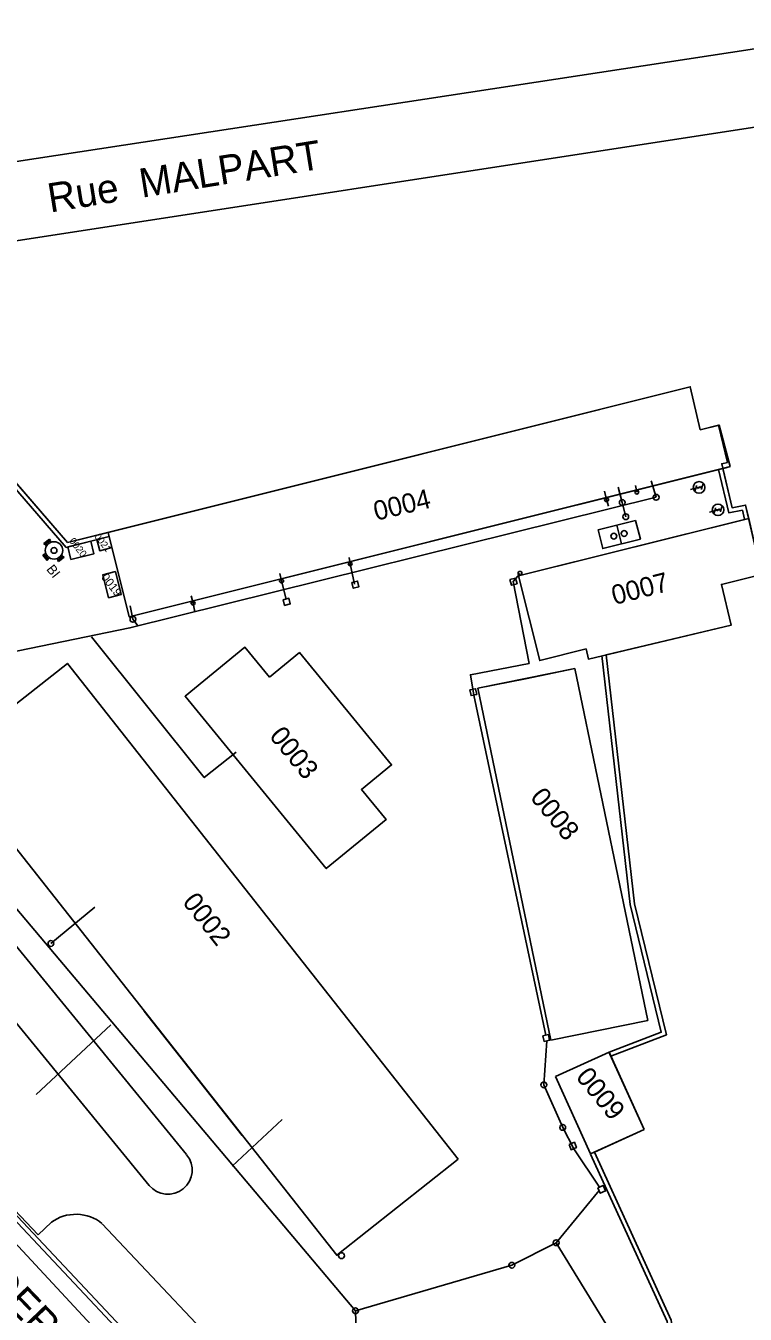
# Model space of a CAD drawing. Extents: x 703432 to 707394, y 7057985 to 7059523.
# Drawn here: x 704507 to 704581.3, y 7058975.3 to 7059108.3 of the extents above; entities that cross this region are included whole.
import ezdxf

# ---------------------------------------------------------------- set-up
doc = ezdxf.new("R2010")
doc.units = 0
for name, color, linetype in [('DH_HACHURE-MOTIF', 7, 'Continuous'), ('DH_TEXTE', 7, 'Continuous'), ('GEOSID_AIRE_AMENAGEE_POLYGONE', 7, 'Continuous'), ('GO_DALLE', 7, 'Continuous'), ('GO_MUR_EXTERIEUR', 7, 'Continuous'), ('IMM_LIMITE PHYSIQUE', 7, 'Continuous'), ('R_PLU_CANALISATION_CL_A', 7, 'Continuous'), ('RES_EAU BASSE PRESSION', 7, 'Continuous'), ('RES_EAU BASSE PRESSION - EQUIP - TEXTE', 7, 'Continuous'), ('RES_INCENDIE - EQUIP - TEXTE', 7, 'Continuous'), ('SID_NUMERO_BATI', 7, 'Continuous'), ('SID_POLYLIGNES_BATI', 7, 'Continuous'), ('SID_POLYLIGNES_IMMEUBLE', 7, 'Continuous'), ('SO_EP_EQUIP', 7, 'Continuous'), ('VOIRIE_BORDURE', 7, 'Continuous'), ('VOIRIE_ROUTE', 7, 'Continuous')]:
    doc.layers.add(name, color=color, linetype=linetype)

msp = doc.modelspace()

# ---------------------------------------------------------------- linework, layer by layer
at = {"layer": 'DH_HACHURE-MOTIF'}
for p, q in [((704553.67, 7059039.96), (704558.58, 7059040.92)), ((704561.21, 7059003.63), (704553.67, 7059039.96)), ((704571.23, 7059005.64), (704561.21, 7059003.63)), ((704561.7, 7058999.87), (704567.23, 7059002.37)), ((704565.31, 7058991.89), (704561.7, 7058999.87)), ((704570.84, 7058994.39), (704565.31, 7058991.89))]:
    msp.add_line(p, q, dxfattribs=at)
for points in [[(704515.58, 7059055.6), (704515.87, 7059054.46), (704517.65, 7059047.3), (704579.31, 7059062.71), (704579.74, 7059062.82), (704578.59, 7059067.1), (704576.65, 7059066.62), (704575.62, 7059071.07), (704538.76, 7059061.85), (704515.47, 7059056.03), (704515.58, 7059055.6)], [(704564.85, 7059044.01), (704565.09, 7059042.95), (704579.84, 7059046.44), (704578.84, 7059050.66), (704582.98, 7059051.69), (704581.66, 7059057.48), (704581.22, 7059057.37), (704557.88, 7059051.53), (704560.06, 7059042.8), (704564.85, 7059044.01)], [(704513.69, 7059055.12), (704511.31, 7059054.53), (704511.63, 7059053.24), (704514.01, 7059053.83), (704513.69, 7059055.12)], [(704515.52, 7059049.28), (704516.81, 7059049.61), (704516.22, 7059051.98), (704514.93, 7059051.66), (704515.52, 7059049.28)], [(704532.15, 7059041.09), (704529.61, 7059044.18), (704523.42, 7059039.11), (704538, 7059021.32), (704544.19, 7059026.39), (704541.65, 7059029.48), (704544.75, 7059032.02), (704535.24, 7059043.62), (704532.15, 7059041.09)], [(704551.65, 7058991.33), (704511.27, 7059042.51), (704505.27, 7059037.77), (704505.89, 7059036.98), (704499.33, 7059031.81), (704539.09, 7058981.42), (704551.65, 7058991.33)], [(704558.58, 7059040.92), (704563.69, 7059041.98), (704571.23, 7059005.64)], [(704567.23, 7059002.37), (704567.32, 7059002.18), (704570.84, 7058994.39)]]:
    msp.add_lwpolyline(points, dxfattribs=at)
at = {"layer": 'GEOSID_AIRE_AMENAGEE_POLYGONE'}
msp.add_lwpolyline([(704514.6, 7059054.14), (704514.32, 7059055.28), (704515.58, 7059055.6), (704515.86, 7059054.46)], close=True, dxfattribs=at)
at = {"layer": 'GO_DALLE'}
msp.add_lwpolyline([(704515.58, 7059055.6), (704515.87, 7059054.46), (704514.6, 7059054.14), (704514.32, 7059055.28)], close=True, dxfattribs=at)
at = {"layer": 'GO_MUR_EXTERIEUR'}
for p, q in [((704575.62, 7059071.07), (704515.47, 7059056.03)), ((704576.65, 7059066.62), (704575.62, 7059071.07)), ((704578.59, 7059067.1), (704576.65, 7059066.62)), ((704579.74, 7059062.82), (704578.59, 7059067.1)), ((704517.65, 7059047.3), (704579.74, 7059062.82)), ((704557.88, 7059051.53), (704581.66, 7059057.48)), ((704515.47, 7059056.03), (704517.65, 7059047.3)), ((704560.06, 7059042.8), (704557.88, 7059051.53)), ((704582.98, 7059051.69), (704578.84, 7059050.66)), ((704578.84, 7059050.66), (704579.84, 7059046.44)), ((704523.42, 7059039.11), (704529.61, 7059044.18)), ((704529.61, 7059044.18), (704532.15, 7059041.09)), ((704532.15, 7059041.09), (704535.24, 7059043.62)), ((704535.24, 7059043.62), (704544.75, 7059032.02)), ((704511.27, 7059042.51), (704505.27, 7059037.77)), ((704551.65, 7058991.33), (704511.27, 7059042.51)), ((704553.67, 7059039.96), (704563.69, 7059041.98)), ((704563.69, 7059041.98), (704571.23, 7059005.64)), ((704561.21, 7059003.63), (704553.67, 7059039.96)), ((704538, 7059021.32), (704523.42, 7059039.11)), ((704499.33, 7059031.81), (704539.09, 7058981.42)), ((704544.75, 7059032.02), (704541.65, 7059029.48)), ((704541.65, 7059029.48), (704544.19, 7059026.39)), ((704544.19, 7059026.39), (704538, 7059021.32)), ((704571.23, 7059005.64), (704561.21, 7059003.63)), ((704561.7, 7058999.87), (704567.23, 7059002.37)), ((704567.23, 7059002.37), (704570.84, 7058994.39)), ((704565.31, 7058991.89), (704561.7, 7058999.87)), ((704570.84, 7058994.39), (704565.31, 7058991.89)), ((704539.09, 7058981.42), (704551.65, 7058991.33))]:
    msp.add_line(p, q, dxfattribs=at)
for points in [[(704511.31, 7059054.53), (704511.63, 7059053.24), (704514.01, 7059053.83), (704513.69, 7059055.12)], [(704516.22, 7059051.98), (704514.93, 7059051.66), (704515.52, 7059049.28), (704516.81, 7059049.61)]]:
    msp.add_lwpolyline(points, close=True, dxfattribs=at)
msp.add_lwpolyline([(704579.84, 7059046.44), (704565.09, 7059042.95), (704564.85, 7059044.01), (704560.06, 7059042.8)], dxfattribs=at)
at = {"layer": 'IMM_LIMITE PHYSIQUE'}
for p, q in [((704499.39, 7059068.01), (704511.13, 7059054.48)), ((704499.74, 7059068.3), (704511.28, 7059054.99)), ((704515.59, 7059055.6), (704511.13, 7059054.48)), ((704515.47, 7059056.03), (704511.28, 7059054.99)), ((704472.61, 7059020.9), (704536.21, 7058953.48)), ((704472.28, 7059020.59), (704535.98, 7058953.07))]:
    msp.add_line(p, q, dxfattribs=at)
for points in [[(704578.55, 7059062.53), (704579.6, 7059058.05), (704581, 7059058.32), (704581.22, 7059057.38)], [(704578.99, 7059062.63), (704579.94, 7059058.58), (704581.34, 7059058.85), (704581.66, 7059057.48)], [(704566.47, 7059043.33), (704569.4, 7059017.61), (704572.62, 7059004.43), (704567.24, 7059002.38)], [(704566.92, 7059043.38), (704569.84, 7059017.69), (704573.15, 7059004.16), (704567.4, 7059001.96)], [(704574.25, 7058967.23), (704573.22, 7058974.58), (704565.32, 7058991.86)], [(704574.7, 7058967.3), (704573.66, 7058974.71), (704565.73, 7058992.05)]]:
    msp.add_lwpolyline(points, dxfattribs=at)
at = {"layer": 'R_PLU_CANALISATION_CL_A'}
for p, q in [((704568.59, 7059059.11), (704568.17, 7059060.71)), ((704570.1, 7059060.19), (704569.97, 7059060.88)), ((704572.09, 7059059.65), (704571.58, 7059061.35)), ((704566.97, 7059059.41), (704566.75, 7059060.27)), ((704566.97, 7059059.41), (704567.18, 7059058.73)), ((704568.59, 7059059.11), (704568.95, 7059057.65)), ((704568.03, 7059056.78), (704568.52, 7059054.84)), ((704540.48, 7059052.79), (704540.36, 7059053.44)), ((704540.48, 7059052.79), (704540.94, 7059050.67)), ((704533.39, 7059051.02), (704533.2, 7059051.8)), ((704558.03, 7059051.8), (704557.33, 7059050.95)), ((704533.39, 7059051.02), (704533.86, 7059049.15)), ((704524.25, 7059048.73), (704524.06, 7059049.47)), ((704524.25, 7059048.73), (704524.43, 7059047.8)), ((704518.04, 7059047.06), (704517.76, 7059048.45)), ((704518.04, 7059047.06), (704518.59, 7059046.36)), ((704553.26, 7059039.24), (704560.68, 7059004.13)), ((704500.69, 7059023.41), (704541.03, 7058975.68)), ((704509.56, 7059013.59), (704514.11, 7059017.35)), ((704519.21, 7059006.61), (704529.33, 7058993.79)), ((704515.74, 7059005.19), (704508.03, 7058998)), ((704533.45, 7058995.41), (704528.29, 7058990.6)), ((704541.33, 7058964.53), (704541.03, 7058975.68))]:
    msp.add_line(p, q, dxfattribs=at)
for points in [[(704572.09, 7059059.65), (704517.73, 7059046.17), (704502.8, 7059043.12)], [(704569.97, 7059057.26), (704570.46, 7059055.32), (704566.58, 7059054.35), (704566.09, 7059056.29), (704569.97, 7059057.26)], [(704556.99, 7059051.16), (704557.57, 7059051.31), (704557.72, 7059050.73), (704557.14, 7059050.58), (704556.99, 7059051.16)], [(704540.65, 7059050.85), (704541.24, 7059051), (704541.38, 7059050.42), (704540.8, 7059050.27), (704540.65, 7059050.85)], [(704557.33, 7059050.95), (704558.96, 7059042.5), (704552.91, 7059041.34), (704553.26, 7059039.24)], [(704533.57, 7059049.08), (704534.15, 7059049.23), (704534.29, 7059048.64), (704533.71, 7059048.5), (704533.57, 7059049.08)], [(704513.75, 7059045.25), (704525.41, 7059030.72), (704528.7, 7059033.35)], [(704552.85, 7059039.77), (704553.43, 7059039.89), (704553.56, 7059039.3), (704552.97, 7059039.18), (704552.85, 7059039.77)], [(704560.38, 7059004.07), (704560.97, 7059004.2), (704561.09, 7059003.61), (704560.51, 7059003.48), (704560.38, 7059004.07)], [(704560.8, 7059003.55), (704560.49, 7058999), (704562.44, 7058994.61), (704563.58, 7058992.41), (704566.24, 7058988.45)], [(704563.09, 7058992.86), (704563.65, 7058993.08), (704563.86, 7058992.52), (704563.3, 7058992.3), (704563.09, 7058992.86)], [(704541.03, 7058975.68), (704557.19, 7058980.38), (704561.77, 7058982.71), (704566.19, 7058988.1)], [(704566.07, 7058988.37), (704566.62, 7058988.61), (704566.86, 7058988.06), (704566.31, 7058987.82), (704566.07, 7058988.37)], [(704561.77, 7058982.71), (704570.05, 7058969.19), (704573.99, 7058967.43)]]:
    msp.add_lwpolyline(points, dxfattribs=at)
for centre, radius in [((704576.53, 7059060.67), 0.6), ((704568.59, 7059059.11), 0.3), ((704572.09, 7059059.65), 0.3), ((704568.95, 7059057.65), 0.3), ((704578.49, 7059058.36), 0.6), ((704567.72, 7059055.64), 0.3), ((704568.79, 7059055.91), 0.3), ((704518.04, 7059047.06), 0.3), ((704509.56, 7059013.59), 0.3), ((704560.49, 7058999), 0.3), ((704562.44, 7058994.61), 0.3), ((704561.77, 7058982.71), 0.3), ((704539.58, 7058981.37), 0.3), ((704557.19, 7058980.38), 0.3), ((704541.03, 7058975.68), 0.3)]:
    msp.add_circle(centre, radius, dxfattribs=at)
at = {"layer": 'RES_EAU BASSE PRESSION'}
for p, q in [((704576.37, 7059060.63), (704576.2, 7059060.58)), ((704576.92, 7059061.02), (704576.78, 7059060.47)), ((704578.33, 7059058.32), (704578.16, 7059058.27)), ((704578.88, 7059058.71), (704578.74, 7059058.16))]:
    msp.add_line(p, q, dxfattribs=at)
at = {"layer": 'RES_EAU BASSE PRESSION - EQUIP - TEXTE'}
for p, q in [((704576.2, 7059060.58), (704575.65, 7059060.44)), ((704576.38, 7059060.56), (704576.35, 7059060.69)), ((704576.7, 7059060.64), (704576.35, 7059060.69)), ((704576.38, 7059060.56), (704576.67, 7059060.77)), ((704576.7, 7059060.64), (704576.67, 7059060.77)), ((704576.69, 7059060.7), (704576.85, 7059060.75)), ((704578.16, 7059058.27), (704577.61, 7059058.13)), ((704578.35, 7059058.25), (704578.31, 7059058.38)), ((704578.66, 7059058.33), (704578.31, 7059058.38)), ((704578.35, 7059058.25), (704578.63, 7059058.46)), ((704578.66, 7059058.33), (704578.63, 7059058.46)), ((704578.65, 7059058.39), (704578.81, 7059058.44))]:
    msp.add_line(p, q, dxfattribs=at)
at = {"layer": 'RES_INCENDIE - EQUIP - TEXTE'}
for p, q in [((704576.27, 7059060.86), (704576.13, 7059060.31)), ((704578.23, 7059058.55), (704578.09, 7059058)), ((704508.84, 7059054.87), (704509.4, 7059055.33)), ((704509.4, 7059055.33), (704509.49, 7059055.21)), ((704508.84, 7059054.87), (704508.93, 7059054.76)), ((704508.93, 7059054.76), (704509.49, 7059055.21)), ((704508.98, 7059054.8), (704509.11, 7059054.64)), ((704509.44, 7059055.18), (704509.57, 7059055.02)), ((704508.72, 7059053.69), (704508.84, 7059053.79)), ((704508.72, 7059053.69), (704509.18, 7059053.13)), ((704508.84, 7059053.79), (704509.29, 7059053.23)), ((704508.87, 7059053.74), (704509.03, 7059053.87)), ((704509.18, 7059053.13), (704509.29, 7059053.23)), ((704509.26, 7059053.28), (704509.41, 7059053.4)), ((704510.18, 7059053.33), (704510.31, 7059053.17)), ((704510.26, 7059053.13), (704510.82, 7059053.59)), ((704510.26, 7059053.13), (704510.36, 7059053.02)), ((704510.36, 7059053.02), (704510.92, 7059053.47)), ((704510.65, 7059053.71), (704510.77, 7059053.55)), ((704510.82, 7059053.59), (704510.92, 7059053.47))]:
    msp.add_line(p, q, dxfattribs=at)
for radius in [0.9, 0.3]:
    msp.add_circle((704509.88, 7059054.17), radius, dxfattribs=at)
at = {"layer": 'SID_POLYLIGNES_BATI'}
for p, q in [((704575.62, 7059071.07), (704515.47, 7059056.03)), ((704576.65, 7059066.62), (704575.62, 7059071.07)), ((704578.59, 7059067.1), (704576.65, 7059066.62)), ((704579.74, 7059062.82), (704578.59, 7059067.1)), ((704517.65, 7059047.3), (704579.74, 7059062.82)), ((704515.47, 7059056.03), (704517.65, 7059047.3)), ((704523.42, 7059039.11), (704529.61, 7059044.18)), ((704529.61, 7059044.18), (704532.15, 7059041.09)), ((704532.15, 7059041.09), (704535.24, 7059043.62)), ((704535.24, 7059043.62), (704544.75, 7059032.02)), ((704511.27, 7059042.51), (704505.27, 7059037.77)), ((704551.65, 7058991.33), (704511.27, 7059042.51)), ((704553.67, 7059039.96), (704563.69, 7059041.98)), ((704563.69, 7059041.98), (704571.23, 7059005.64)), ((704561.21, 7059003.63), (704553.67, 7059039.96)), ((704538, 7059021.32), (704523.42, 7059039.11)), ((704499.33, 7059031.81), (704539.09, 7058981.42)), ((704544.75, 7059032.02), (704541.65, 7059029.48)), ((704541.65, 7059029.48), (704544.19, 7059026.39)), ((704544.19, 7059026.39), (704538, 7059021.32)), ((704571.23, 7059005.64), (704561.21, 7059003.63)), ((704561.7, 7058999.87), (704567.23, 7059002.37)), ((704567.23, 7059002.37), (704570.84, 7058994.39)), ((704565.31, 7058991.89), (704561.7, 7058999.87)), ((704570.84, 7058994.39), (704565.31, 7058991.89)), ((704539.09, 7058981.42), (704551.65, 7058991.33))]:
    msp.add_line(p, q, dxfattribs=at)
for points in [[(704514.6, 7059054.14), (704514.32, 7059055.28), (704515.58, 7059055.6), (704515.87, 7059054.46)], [(704511.31, 7059054.53), (704511.63, 7059053.24), (704514.01, 7059053.83), (704513.69, 7059055.12)], [(704516.22, 7059051.98), (704514.93, 7059051.66), (704515.52, 7059049.28), (704516.81, 7059049.61)]]:
    msp.add_lwpolyline(points, close=True, dxfattribs=at)
at = {"layer": 'SID_POLYLIGNES_IMMEUBLE'}
for p, q in [((704511.28, 7059054.99), (704575.62, 7059071.07)), ((704575.62, 7059071.07), (704576.65, 7059066.62)), ((704576.65, 7059066.62), (704578.55, 7059067.1)), ((704511.28, 7059054.99), (704511.28, 7059054.99)), ((704582.98, 7059051.69), (704578.84, 7059050.66)), ((704578.84, 7059050.66), (704579.84, 7059046.44)), ((704535.98, 7058953.07), (704446.77, 7059047.64)), ((704579.84, 7059046.44), (704566.92, 7059043.39)), ((704573.15, 7059004.16), (704567.4, 7059001.96)), ((704567.4, 7059001.96), (704570.84, 7058994.39)), ((704570.84, 7058994.39), (704565.73, 7058992.05)), ((704565.73, 7058992.05), (704573.66, 7058974.71))]:
    msp.add_line(p, q, dxfattribs=at)
for points in [[(704492.42, 7059080.39), (704493.18, 7059075.86), (704511.28, 7059054.99)], [(704578.55, 7059067.1), (704579.45, 7059063.26), (704578.88, 7059063.11), (704579.94, 7059058.58), (704581.34, 7059058.85), (704582.98, 7059051.69)], [(704566.92, 7059043.39), (704569.84, 7059017.69), (704573.15, 7059004.16)]]:
    msp.add_lwpolyline(points, dxfattribs=at)
at = {"layer": 'SO_EP_EQUIP'}
for centre in [(704566.97, 7059059.41), (704570.1, 7059060.19), (704540.48, 7059052.79), (704558.03, 7059051.8), (704533.39, 7059051.02), (704524.25, 7059048.73)]:
    msp.add_circle(centre, 0.2, dxfattribs=at)
at = {"layer": 'VOIRIE_BORDURE'}
for p, q in [((704504.13, 7059015.53), (704523.58, 7058991.8)), ((704500.26, 7059012.37), (704519.71, 7058988.63)), ((704490.3, 7059002.52), (704508.23, 7058983.51)), ((704508.23, 7058983.51), (704509.63, 7058984.82)), ((704514.85, 7058984.67), (704525.12, 7058973.78))]:
    msp.add_line(p, q, dxfattribs=at)
msp.add_arc((704521.65, 7058990.21), 2.5, 219.3307, 39.3307, dxfattribs=at)
msp.add_ellipse((704512.15, 7058982.64), major_axis=(-3.68, 0), ratio=0.816097, start_param=3.897855, end_param=5.468654, dxfattribs=at)
at = {"layer": 'VOIRIE_ROUTE'}
msp.add_line((704482.54, 7059007.66), (704534.87, 7058951.59), dxfattribs=at)
for points in [[(704439.21, 7059062.29), (704466.43, 7059084.66), (704472.47, 7059087.95), (704480.92, 7059090.49), (704597.81, 7059108.33)], [(704599.06, 7059100.45), (704481.77, 7059082.41), (704472.42, 7059078.45), (704444.83, 7059056.07)]]:
    msp.add_lwpolyline(points, dxfattribs=at)

# ---------------------------------------------------------------- texts
at = {"layer": 'DH_TEXTE'}
for s, rotation, p in [('Rue  MALPART', 9.1668, (704509.48, 7059089.04)), ('Rue LYDERIC', 313.8024, (704493.48, 7058988.15))]:
    msp.add_text(s, height=3, rotation=rotation, dxfattribs=at).set_placement(p)
at = {"layer": 'RES_INCENDIE - EQUIP - TEXTE'}
msp.add_text('BI', height=1, rotation=308.2727, dxfattribs=at).set_placement((704509.04, 7059052.21))
at = {"layer": 'SID_NUMERO_BATI'}
for s, height, rotation, p in [('0004', 2, 13.5243, (704543.16, 7059057.22)), ('0020', 0.738, 308.0308, (704511.4, 7059055.12)), ('0021', 0.702, 308.0308, (704514.01, 7059055.58)), ('0019', 0.866, 308.0308, (704514.7, 7059051.37)), ('0007', 2, 14.5051, (704567.78, 7059048.53)), ('0003', 2, 309.3307, (704532.04, 7059034.97)), ('0008', 2, 309.3307, (704558.99, 7059028.65)), ('0002', 2, 308.2727, (704523.07, 7059017.85)), ('0009', 2, 309.3307, (704563.71, 7058999.79))]:
    msp.add_text(s, height=height, rotation=rotation, dxfattribs=at).set_placement(p)

doc.saveas('drawing.dxf')
